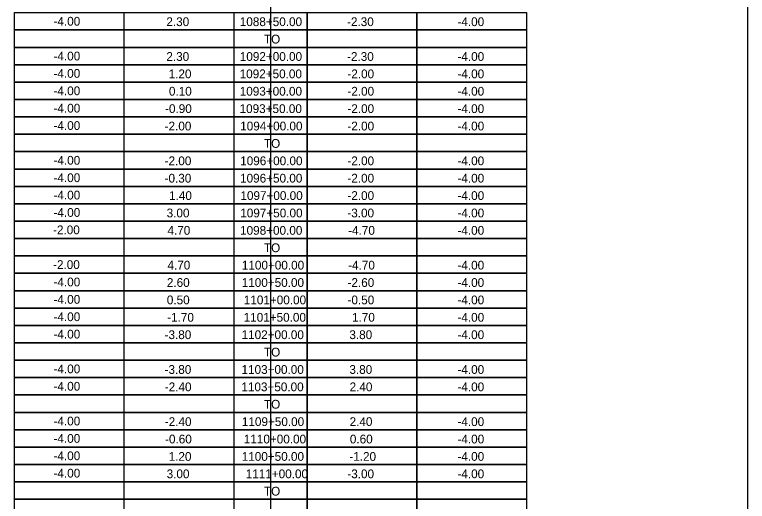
# Model space of a CAD drawing. Extents: x 1026502 to 1027102, y 781811 to 782040.
# Drawn here: x 1026950.62 to 1026990.71, y 781842.59 to 781869.21 of the extents above; entities that cross this region are included whole.
import ezdxf

# ---------------------------------------------------------------- set-up
doc = ezdxf.new("R2010")
doc.units = 0
doc.layers.add('BORDER', color=7, linetype='Continuous')
doc.layers.add('DIMENSIONS', color=7, linetype='Continuous')

msp = doc.modelspace()

# ---------------------------------------------------------------- linework, layer by layer
at = {"layer": 'BORDER'}
for p, q in [((1026964.619, 781922.543), (1026964.619, 781816.098)), ((1026990.71, 781922.543), (1026990.71, 781816.098)), ((1026953.619, 781868.37), (1026950.619, 781868.37)), ((1026953.619, 781868.37), (1026950.619, 781868.37)), ((1026953.619, 781868.37), (1026956.619, 781868.37)), ((1026953.619, 781867.419), (1026950.619, 781867.419)), ((1026953.619, 781867.419), (1026950.619, 781867.419)), ((1026953.619, 781867.419), (1026956.619, 781867.419)), ((1026953.619, 781866.469), (1026950.619, 781866.469)), ((1026953.619, 781866.469), (1026950.619, 781866.469)), ((1026953.619, 781866.469), (1026956.619, 781866.469)), ((1026953.619, 781865.519), (1026950.619, 781865.519)), ((1026953.619, 781865.519), (1026950.619, 781865.519)), ((1026953.619, 781865.519), (1026956.619, 781865.519)), ((1026953.619, 781864.568), (1026950.619, 781864.568)), ((1026953.619, 781864.568), (1026950.619, 781864.568)), ((1026953.619, 781864.568), (1026956.619, 781864.568)), ((1026953.619, 781863.618), (1026950.619, 781863.618)), ((1026953.619, 781863.618), (1026950.619, 781863.618)), ((1026953.619, 781863.618), (1026956.619, 781863.618)), ((1026953.619, 781862.667), (1026950.619, 781862.667)), ((1026953.619, 781862.667), (1026950.619, 781862.667)), ((1026953.619, 781862.667), (1026956.619, 781862.667)), ((1026953.619, 781861.717), (1026950.619, 781861.717)), ((1026953.619, 781861.717), (1026950.619, 781861.717)), ((1026953.619, 781861.717), (1026956.619, 781861.717)), ((1026953.619, 781860.767), (1026950.619, 781860.767)), ((1026953.619, 781860.767), (1026950.619, 781860.767)), ((1026953.619, 781860.767), (1026956.619, 781860.767)), ((1026953.619, 781859.816), (1026950.619, 781859.816)), ((1026953.619, 781859.816), (1026950.619, 781859.816)), ((1026953.619, 781859.816), (1026956.619, 781859.816)), ((1026953.619, 781858.866), (1026950.619, 781858.866)), ((1026953.619, 781858.866), (1026950.619, 781858.866)), ((1026953.619, 781858.866), (1026956.619, 781858.866)), ((1026953.619, 781857.915), (1026950.619, 781857.915)), ((1026953.619, 781857.915), (1026950.619, 781857.915)), ((1026953.619, 781857.915), (1026956.619, 781857.915)), ((1026953.619, 781856.965), (1026950.619, 781856.965)), ((1026953.619, 781856.965), (1026950.619, 781856.965)), ((1026953.619, 781856.965), (1026956.619, 781856.965)), ((1026953.619, 781856.015), (1026950.619, 781856.015)), ((1026953.619, 781856.015), (1026950.619, 781856.015)), ((1026953.619, 781856.015), (1026956.619, 781856.015)), ((1026953.619, 781855.064), (1026950.619, 781855.064)), ((1026953.619, 781855.064), (1026950.619, 781855.064)), ((1026953.619, 781855.064), (1026956.619, 781855.064)), ((1026953.619, 781854.114), (1026950.619, 781854.114)), ((1026953.619, 781854.114), (1026950.619, 781854.114)), ((1026953.619, 781854.114), (1026956.619, 781854.114)), ((1026953.619, 781853.163), (1026950.619, 781853.163)), ((1026953.619, 781853.163), (1026950.619, 781853.163)), ((1026953.619, 781853.163), (1026956.619, 781853.163)), ((1026953.619, 781852.213), (1026950.619, 781852.213)), ((1026953.619, 781852.213), (1026950.619, 781852.213)), ((1026953.619, 781852.213), (1026956.619, 781852.213)), ((1026953.619, 781851.263), (1026950.619, 781851.263)), ((1026953.619, 781851.263), (1026950.619, 781851.263)), ((1026953.619, 781851.263), (1026956.619, 781851.263)), ((1026953.619, 781850.312), (1026950.619, 781850.312)), ((1026953.619, 781850.312), (1026950.619, 781850.312)), ((1026953.619, 781850.312), (1026956.619, 781850.312)), ((1026953.619, 781849.362), (1026950.619, 781849.362)), ((1026953.619, 781849.362), (1026950.619, 781849.362)), ((1026953.619, 781849.362), (1026956.619, 781849.362)), ((1026953.619, 781848.411), (1026950.619, 781848.411)), ((1026953.619, 781848.411), (1026950.619, 781848.411)), ((1026953.619, 781848.411), (1026956.619, 781848.411)), ((1026953.619, 781847.461), (1026950.619, 781847.461)), ((1026953.619, 781847.461), (1026950.619, 781847.461)), ((1026953.619, 781847.461), (1026956.619, 781847.461)), ((1026953.619, 781846.511), (1026950.619, 781846.511)), ((1026953.619, 781846.511), (1026950.619, 781846.511)), ((1026953.619, 781846.511), (1026956.619, 781846.511)), ((1026953.619, 781845.56), (1026950.619, 781845.56)), ((1026953.619, 781845.56), (1026950.619, 781845.56)), ((1026953.619, 781845.56), (1026956.619, 781845.56)), ((1026953.619, 781844.61), (1026950.619, 781844.61)), ((1026953.619, 781844.61), (1026950.619, 781844.61)), ((1026953.619, 781844.61), (1026956.619, 781844.61)), ((1026953.619, 781843.659), (1026950.619, 781843.659)), ((1026953.619, 781843.659), (1026950.619, 781843.659)), ((1026953.619, 781843.659), (1026956.619, 781843.659)), ((1026953.619, 781842.709), (1026950.619, 781842.709)), ((1026953.619, 781842.709), (1026950.619, 781842.709)), ((1026953.619, 781842.709), (1026956.619, 781842.709))]:
    msp.add_line(p, q, dxfattribs=at)
for points in [[(1026950.619, 781869.32), (1026978.619, 781869.32), (1026978.619, 781868.37), (1026950.619, 781868.37)], [(1026950.619, 781868.37), (1026978.619, 781868.37), (1026978.619, 781867.419), (1026950.619, 781867.419)], [(1026950.619, 781867.419), (1026978.619, 781867.419), (1026978.619, 781866.469), (1026950.619, 781866.469)], [(1026950.619, 781866.469), (1026978.619, 781866.469), (1026978.619, 781865.519), (1026950.619, 781865.519)], [(1026950.619, 781865.519), (1026978.619, 781865.519), (1026978.619, 781864.568), (1026950.619, 781864.568)], [(1026950.619, 781864.568), (1026978.619, 781864.568), (1026978.619, 781863.618), (1026950.619, 781863.618)], [(1026950.619, 781863.618), (1026978.619, 781863.618), (1026978.619, 781862.667), (1026950.619, 781862.667)], [(1026950.619, 781862.667), (1026978.619, 781862.667), (1026978.619, 781861.717), (1026950.619, 781861.717)], [(1026950.619, 781861.717), (1026978.619, 781861.717), (1026978.619, 781860.767), (1026950.619, 781860.767)], [(1026950.619, 781860.767), (1026978.619, 781860.767), (1026978.619, 781859.816), (1026950.619, 781859.816)], [(1026950.619, 781859.816), (1026978.619, 781859.816), (1026978.619, 781858.866), (1026950.619, 781858.866)], [(1026950.619, 781858.866), (1026978.619, 781858.866), (1026978.619, 781857.915), (1026950.619, 781857.915)], [(1026950.619, 781857.915), (1026978.619, 781857.915), (1026978.619, 781856.965), (1026950.619, 781856.965)], [(1026950.619, 781856.965), (1026978.619, 781856.965), (1026978.619, 781856.015), (1026950.619, 781856.015)], [(1026950.619, 781856.015), (1026978.619, 781856.015), (1026978.619, 781855.064), (1026950.619, 781855.064)], [(1026950.619, 781855.064), (1026978.619, 781855.064), (1026978.619, 781854.114), (1026950.619, 781854.114)], [(1026950.619, 781854.114), (1026978.619, 781854.114), (1026978.619, 781853.163), (1026950.619, 781853.163)], [(1026950.619, 781853.163), (1026978.619, 781853.163), (1026978.619, 781852.213), (1026950.619, 781852.213)], [(1026950.619, 781852.213), (1026978.619, 781852.213), (1026978.619, 781851.263), (1026950.619, 781851.263)], [(1026950.619, 781851.263), (1026978.619, 781851.263), (1026978.619, 781850.312), (1026950.619, 781850.312)], [(1026950.619, 781850.312), (1026978.619, 781850.312), (1026978.619, 781849.362), (1026950.619, 781849.362)], [(1026950.619, 781849.362), (1026978.619, 781849.362), (1026978.619, 781848.411), (1026950.619, 781848.411)], [(1026950.619, 781848.411), (1026978.619, 781848.411), (1026978.619, 781847.461), (1026950.619, 781847.461)], [(1026950.619, 781847.461), (1026978.619, 781847.461), (1026978.619, 781846.511), (1026950.619, 781846.511)], [(1026950.619, 781846.511), (1026978.619, 781846.511), (1026978.619, 781845.56), (1026950.619, 781845.56)], [(1026950.619, 781845.56), (1026978.619, 781845.56), (1026978.619, 781844.61), (1026950.619, 781844.61)], [(1026950.619, 781844.61), (1026978.619, 781844.61), (1026978.619, 781843.659), (1026950.619, 781843.659)], [(1026950.619, 781843.659), (1026978.619, 781843.659), (1026978.619, 781842.709), (1026950.619, 781842.709)], [(1026950.619, 781842.709), (1026978.619, 781842.709), (1026978.619, 781841.759), (1026950.619, 781841.759)]]:
    msp.add_lwpolyline(points, close=True, dxfattribs=at)
for points in [[(1026962.619, 781869.32), (1026962.619, 781868.37), (1026956.619, 781868.37), (1026956.619, 781869.32)], [(1026966.619, 781869.32), (1026966.619, 781868.37), (1026962.619, 781868.37)], [(1026972.619, 781869.32), (1026972.619, 781868.37), (1026966.619, 781868.37), (1026966.619, 781869.32)], [(1026978.619, 781869.32), (1026978.619, 781868.37), (1026972.619, 781868.37), (1026972.619, 781869.32)], [(1026962.619, 781868.37), (1026962.619, 781867.419), (1026956.619, 781867.419), (1026956.619, 781868.37)], [(1026966.619, 781868.37), (1026966.619, 781867.419), (1026962.619, 781867.419)], [(1026972.619, 781868.37), (1026972.619, 781867.419), (1026966.619, 781867.419), (1026966.619, 781868.37)], [(1026978.619, 781868.37), (1026978.619, 781867.419), (1026972.619, 781867.419), (1026972.619, 781868.37)], [(1026962.619, 781867.419), (1026962.619, 781866.469), (1026956.619, 781866.469), (1026956.619, 781867.419)], [(1026966.619, 781867.419), (1026966.619, 781866.469), (1026962.619, 781866.469)], [(1026972.619, 781867.419), (1026972.619, 781866.469), (1026966.619, 781866.469), (1026966.619, 781867.419)], [(1026978.619, 781867.419), (1026978.619, 781866.469), (1026972.619, 781866.469), (1026972.619, 781867.419)], [(1026962.619, 781866.469), (1026962.619, 781865.519), (1026956.619, 781865.519), (1026956.619, 781866.469)], [(1026966.619, 781866.469), (1026966.619, 781865.519), (1026962.619, 781865.519)], [(1026972.619, 781866.469), (1026972.619, 781865.519), (1026966.619, 781865.519), (1026966.619, 781866.469)], [(1026978.619, 781866.469), (1026978.619, 781865.519), (1026972.619, 781865.519), (1026972.619, 781866.469)], [(1026962.619, 781865.519), (1026962.619, 781864.568), (1026956.619, 781864.568), (1026956.619, 781865.519)], [(1026966.619, 781865.519), (1026966.619, 781864.568), (1026962.619, 781864.568)], [(1026972.619, 781865.519), (1026972.619, 781864.568), (1026966.619, 781864.568), (1026966.619, 781865.519)], [(1026978.619, 781865.519), (1026978.619, 781864.568), (1026972.619, 781864.568), (1026972.619, 781865.519)], [(1026962.619, 781864.568), (1026962.619, 781863.618), (1026956.619, 781863.618), (1026956.619, 781864.568)], [(1026966.619, 781864.568), (1026966.619, 781863.618), (1026962.619, 781863.618)], [(1026972.619, 781864.568), (1026972.619, 781863.618), (1026966.619, 781863.618), (1026966.619, 781864.568)], [(1026978.619, 781864.568), (1026978.619, 781863.618), (1026972.619, 781863.618), (1026972.619, 781864.568)], [(1026962.619, 781863.618), (1026962.619, 781862.667), (1026956.619, 781862.667), (1026956.619, 781863.618)], [(1026966.619, 781863.618), (1026966.619, 781862.667), (1026962.619, 781862.667)], [(1026972.619, 781863.618), (1026972.619, 781862.667), (1026966.619, 781862.667), (1026966.619, 781863.618)], [(1026978.619, 781863.618), (1026978.619, 781862.667), (1026972.619, 781862.667), (1026972.619, 781863.618)], [(1026962.619, 781862.667), (1026962.619, 781861.717), (1026956.619, 781861.717), (1026956.619, 781862.667)], [(1026966.619, 781862.667), (1026966.619, 781861.717), (1026962.619, 781861.717)], [(1026972.619, 781862.667), (1026972.619, 781861.717), (1026966.619, 781861.717), (1026966.619, 781862.667)], [(1026978.619, 781862.667), (1026978.619, 781861.717), (1026972.619, 781861.717), (1026972.619, 781862.667)], [(1026962.619, 781861.717), (1026962.619, 781860.767), (1026956.619, 781860.767), (1026956.619, 781861.717)], [(1026966.619, 781861.717), (1026966.619, 781860.767), (1026962.619, 781860.767)], [(1026972.619, 781861.717), (1026972.619, 781860.767), (1026966.619, 781860.767), (1026966.619, 781861.717)], [(1026978.619, 781861.717), (1026978.619, 781860.767), (1026972.619, 781860.767), (1026972.619, 781861.717)], [(1026962.619, 781860.767), (1026962.619, 781859.816), (1026956.619, 781859.816), (1026956.619, 781860.767)], [(1026966.619, 781860.767), (1026966.619, 781859.816), (1026962.619, 781859.816)], [(1026972.619, 781860.767), (1026972.619, 781859.816), (1026966.619, 781859.816), (1026966.619, 781860.767)], [(1026978.619, 781860.767), (1026978.619, 781859.816), (1026972.619, 781859.816), (1026972.619, 781860.767)], [(1026962.619, 781859.816), (1026962.619, 781858.866), (1026956.619, 781858.866), (1026956.619, 781859.816)], [(1026966.619, 781859.816), (1026966.619, 781858.866), (1026962.619, 781858.866)], [(1026972.619, 781859.816), (1026972.619, 781858.866), (1026966.619, 781858.866), (1026966.619, 781859.816)], [(1026978.619, 781859.816), (1026978.619, 781858.866), (1026972.619, 781858.866), (1026972.619, 781859.816)], [(1026962.619, 781858.866), (1026962.619, 781857.915), (1026956.619, 781857.915), (1026956.619, 781858.866)], [(1026966.619, 781858.866), (1026966.619, 781857.915), (1026962.619, 781857.915)], [(1026972.619, 781858.866), (1026972.619, 781857.915), (1026966.619, 781857.915), (1026966.619, 781858.866)], [(1026978.619, 781858.866), (1026978.619, 781857.915), (1026972.619, 781857.915), (1026972.619, 781858.866)], [(1026962.619, 781857.915), (1026962.619, 781856.965), (1026956.619, 781856.965), (1026956.619, 781857.915)], [(1026966.619, 781857.915), (1026966.619, 781856.965), (1026962.619, 781856.965)], [(1026972.619, 781857.915), (1026972.619, 781856.965), (1026966.619, 781856.965), (1026966.619, 781857.915)], [(1026978.619, 781857.915), (1026978.619, 781856.965), (1026972.619, 781856.965), (1026972.619, 781857.915)], [(1026962.619, 781856.965), (1026962.619, 781856.015), (1026956.619, 781856.015), (1026956.619, 781856.965)], [(1026966.619, 781856.965), (1026966.619, 781856.015), (1026962.619, 781856.015)], [(1026972.619, 781856.965), (1026972.619, 781856.015), (1026966.619, 781856.015), (1026966.619, 781856.965)], [(1026978.619, 781856.965), (1026978.619, 781856.015), (1026972.619, 781856.015), (1026972.619, 781856.965)], [(1026962.619, 781856.015), (1026962.619, 781855.064), (1026956.619, 781855.064), (1026956.619, 781856.015)], [(1026966.619, 781856.015), (1026966.619, 781855.064), (1026962.619, 781855.064)], [(1026972.619, 781856.015), (1026972.619, 781855.064), (1026966.619, 781855.064), (1026966.619, 781856.015)], [(1026978.619, 781856.015), (1026978.619, 781855.064), (1026972.619, 781855.064), (1026972.619, 781856.015)], [(1026962.619, 781855.064), (1026962.619, 781854.114), (1026956.619, 781854.114), (1026956.619, 781855.064)], [(1026966.619, 781855.064), (1026966.619, 781854.114), (1026962.619, 781854.114)], [(1026972.619, 781855.064), (1026972.619, 781854.114), (1026966.619, 781854.114), (1026966.619, 781855.064)], [(1026978.619, 781855.064), (1026978.619, 781854.114), (1026972.619, 781854.114), (1026972.619, 781855.064)], [(1026962.619, 781854.114), (1026962.619, 781853.163), (1026956.619, 781853.163), (1026956.619, 781854.114)], [(1026966.619, 781854.114), (1026966.619, 781853.163), (1026962.619, 781853.163)], [(1026972.619, 781854.114), (1026972.619, 781853.163), (1026966.619, 781853.163), (1026966.619, 781854.114)], [(1026978.619, 781854.114), (1026978.619, 781853.163), (1026972.619, 781853.163), (1026972.619, 781854.114)], [(1026962.619, 781853.163), (1026962.619, 781852.213), (1026956.619, 781852.213), (1026956.619, 781853.163)], [(1026966.619, 781853.163), (1026966.619, 781852.213), (1026962.619, 781852.213)], [(1026972.619, 781853.163), (1026972.619, 781852.213), (1026966.619, 781852.213), (1026966.619, 781853.163)], [(1026978.619, 781853.163), (1026978.619, 781852.213), (1026972.619, 781852.213), (1026972.619, 781853.163)], [(1026962.619, 781852.213), (1026962.619, 781851.263), (1026956.619, 781851.263), (1026956.619, 781852.213)], [(1026966.619, 781852.213), (1026966.619, 781851.263), (1026962.619, 781851.263)], [(1026972.619, 781852.213), (1026972.619, 781851.263), (1026966.619, 781851.263), (1026966.619, 781852.213)], [(1026978.619, 781852.213), (1026978.619, 781851.263), (1026972.619, 781851.263), (1026972.619, 781852.213)], [(1026962.619, 781851.263), (1026962.619, 781850.312), (1026956.619, 781850.312), (1026956.619, 781851.263)], [(1026966.619, 781851.263), (1026966.619, 781850.312), (1026962.619, 781850.312)], [(1026972.619, 781851.263), (1026972.619, 781850.312), (1026966.619, 781850.312), (1026966.619, 781851.263)], [(1026978.619, 781851.263), (1026978.619, 781850.312), (1026972.619, 781850.312), (1026972.619, 781851.263)], [(1026962.619, 781850.312), (1026962.619, 781849.362), (1026956.619, 781849.362), (1026956.619, 781850.312)], [(1026966.619, 781850.312), (1026966.619, 781849.362), (1026962.619, 781849.362)], [(1026972.619, 781850.312), (1026972.619, 781849.362), (1026966.619, 781849.362), (1026966.619, 781850.312)], [(1026978.619, 781850.312), (1026978.619, 781849.362), (1026972.619, 781849.362), (1026972.619, 781850.312)], [(1026962.619, 781849.362), (1026962.619, 781848.411), (1026956.619, 781848.411), (1026956.619, 781849.362)], [(1026966.619, 781849.362), (1026966.619, 781848.411), (1026962.619, 781848.411)], [(1026972.619, 781849.362), (1026972.619, 781848.411), (1026966.619, 781848.411), (1026966.619, 781849.362)], [(1026978.619, 781849.362), (1026978.619, 781848.411), (1026972.619, 781848.411), (1026972.619, 781849.362)], [(1026962.619, 781848.411), (1026962.619, 781847.461), (1026956.619, 781847.461), (1026956.619, 781848.411)], [(1026966.619, 781848.411), (1026966.619, 781847.461), (1026962.619, 781847.461)], [(1026972.619, 781848.411), (1026972.619, 781847.461), (1026966.619, 781847.461), (1026966.619, 781848.411)], [(1026978.619, 781848.411), (1026978.619, 781847.461), (1026972.619, 781847.461), (1026972.619, 781848.411)], [(1026962.619, 781847.461), (1026962.619, 781846.511), (1026956.619, 781846.511), (1026956.619, 781847.461)], [(1026966.619, 781847.461), (1026966.619, 781846.511), (1026962.619, 781846.511)], [(1026972.619, 781847.461), (1026972.619, 781846.511), (1026966.619, 781846.511), (1026966.619, 781847.461)], [(1026978.619, 781847.461), (1026978.619, 781846.511), (1026972.619, 781846.511), (1026972.619, 781847.461)], [(1026962.619, 781846.511), (1026962.619, 781845.56), (1026956.619, 781845.56), (1026956.619, 781846.511)], [(1026966.619, 781846.511), (1026966.619, 781845.56), (1026962.619, 781845.56)], [(1026972.619, 781846.511), (1026972.619, 781845.56), (1026966.619, 781845.56), (1026966.619, 781846.511)], [(1026978.619, 781846.511), (1026978.619, 781845.56), (1026972.619, 781845.56), (1026972.619, 781846.511)], [(1026962.619, 781845.56), (1026962.619, 781844.61), (1026956.619, 781844.61), (1026956.619, 781845.56)], [(1026966.619, 781845.56), (1026966.619, 781844.61), (1026962.619, 781844.61)], [(1026972.619, 781845.56), (1026972.619, 781844.61), (1026966.619, 781844.61), (1026966.619, 781845.56)], [(1026978.619, 781845.56), (1026978.619, 781844.61), (1026972.619, 781844.61), (1026972.619, 781845.56)], [(1026962.619, 781844.61), (1026962.619, 781843.659), (1026956.619, 781843.659), (1026956.619, 781844.61)], [(1026966.619, 781844.61), (1026966.619, 781843.659), (1026962.619, 781843.659)], [(1026972.619, 781844.61), (1026972.619, 781843.659), (1026966.619, 781843.659), (1026966.619, 781844.61)], [(1026978.619, 781844.61), (1026978.619, 781843.659), (1026972.619, 781843.659), (1026972.619, 781844.61)], [(1026962.619, 781843.659), (1026962.619, 781842.709), (1026956.619, 781842.709), (1026956.619, 781843.659)], [(1026966.619, 781843.659), (1026966.619, 781842.709), (1026962.619, 781842.709)], [(1026972.619, 781843.659), (1026972.619, 781842.709), (1026966.619, 781842.709), (1026966.619, 781843.659)], [(1026978.619, 781843.659), (1026978.619, 781842.709), (1026972.619, 781842.709), (1026972.619, 781843.659)], [(1026962.619, 781842.709), (1026962.619, 781841.759), (1026956.619, 781841.759), (1026956.619, 781842.709)], [(1026966.619, 781842.709), (1026966.619, 781841.759), (1026962.619, 781841.759)], [(1026972.619, 781842.709), (1026972.619, 781841.759), (1026966.619, 781841.759), (1026966.619, 781842.709)], [(1026978.619, 781842.709), (1026978.619, 781841.759), (1026972.619, 781841.759), (1026972.619, 781842.709)]]:
    msp.add_lwpolyline(points, dxfattribs=at)

# ---------------------------------------------------------------- texts
at = {"layer": 'DIMENSIONS'}
for s, p in [('-4.00', (1026952.745, 781868.605)), ('2.30', (1026958.92, 781868.581)), ('1088+50.00', (1026962.937, 781868.581)), ('-2.30', (1026968.806, 781868.581)), ('-4.00', (1026974.848, 781868.581)), ('TO', (1026964.26, 781867.63)), ('-4.00', (1026952.745, 781866.704)), ('2.30', (1026958.92, 781866.679)), ('1092+00.00', (1026962.938, 781866.679)), ('-2.30', (1026968.806, 781866.679)), ('-4.00', (1026974.848, 781866.679)), ('-4.00', (1026952.745, 781865.754)), ('1.20', (1026959.044, 781865.729)), ('1092+50.00', (1026962.93, 781865.729)), ('-2.00', (1026968.825, 781865.729)), ('-4.00', (1026974.848, 781865.729)), ('-4.00', (1026952.745, 781864.803)), ('0.10', (1026959.06, 781864.778)), ('1093+00.00', (1026962.934, 781864.778)), ('-2.00', (1026968.825, 781864.778)), ('-4.00', (1026974.848, 781864.778)), ('-4.00', (1026952.745, 781863.853)), ('-0.90', (1026958.848, 781863.827)), ('1093+50.00', (1026962.926, 781863.827)), ('-2.00', (1026968.825, 781863.827)), ('-4.00', (1026974.848, 781863.827)), ('-4.00', (1026952.745, 781862.903)), ('-2.00', (1026958.825, 781862.876)), ('1094+00.00', (1026962.96, 781862.876)), ('-2.00', (1026968.825, 781862.876)), ('-4.00', (1026974.848, 781862.876)), ('TO', (1026964.26, 781861.925)), ('-4.00', (1026952.745, 781861.002)), ('-2.00', (1026958.825, 781860.974)), ('1096+00.00', (1026962.96, 781860.974)), ('-2.00', (1026968.825, 781860.974)), ('-4.00', (1026974.848, 781860.974)), ('-4.00', (1026952.745, 781860.051)), ('-0.30', (1026958.822, 781860.024)), ('1096+50.00', (1026962.953, 781860.024)), ('-2.00', (1026968.825, 781860.024)), ('-4.00', (1026974.848, 781860.024)), ('-4.00', (1026952.745, 781859.101)), ('1.40', (1026959.067, 781859.073)), ('1097+00.00', (1026962.972, 781859.073)), ('-2.00', (1026968.825, 781859.073)), ('-4.00', (1026974.848, 781859.073)), ('-4.00', (1026952.745, 781858.151)), ('3.00', (1026958.935, 781858.122)), ('1097+50.00', (1026962.964, 781858.122)), ('-3.00', (1026968.822, 781858.122)), ('-4.00', (1026974.848, 781858.122)), ('-2.00', (1026952.72, 781857.2)), ('4.70', (1026958.98, 781857.171)), ('1098+00.00', (1026962.953, 781857.171)), ('-4.70', (1026968.867, 781857.171)), ('-4.00', (1026974.848, 781857.171)), ('TO', (1026964.26, 781856.22)), ('-2.00', (1026952.72, 781855.299)), ('4.70', (1026958.98, 781855.269)), ('1100+00.00', (1026963.051, 781855.269)), ('-4.70', (1026968.867, 781855.269)), ('-4.00', (1026974.848, 781855.269)), ('-4.00', (1026952.745, 781854.349)), ('2.60', (1026958.946, 781854.319)), ('1100+50.00', (1026963.043, 781854.319)), ('-2.60', (1026968.833, 781854.319)), ('-4.00', (1026974.848, 781854.319)), ('-4.00', (1026952.745, 781853.399)), ('0.50', (1026958.946, 781853.368)), ('1101+00.00', (1026963.157, 781853.368)), ('-0.50', (1026968.833, 781853.368)), ('-4.00', (1026974.848, 781853.368)), ('-4.00', (1026952.745, 781852.448)), ('-1.70', (1026958.965, 781852.417)), ('1101+50.00', (1026963.149, 781852.417)), ('1.70', (1026969.078, 781852.417)), ('-4.00', (1026974.848, 781852.417)), ('-4.00', (1026952.745, 781851.498)), ('-3.80', (1026958.822, 781851.466)), ('1102+00.00', (1026963.036, 781851.466)), ('3.80', (1026968.935, 781851.466)), ('-4.00', (1026974.848, 781851.466)), ('TO', (1026964.26, 781850.515)), ('-4.00', (1026952.745, 781849.597)), ('-3.80', (1026958.822, 781849.564)), ('1103+00.00', (1026963.032, 781849.564)), ('3.80', (1026968.935, 781849.564)), ('-4.00', (1026974.848, 781849.564)), ('-4.00', (1026952.745, 781848.647)), ('-2.40', (1026958.833, 781848.614)), ('1103+50.00', (1026963.024, 781848.614)), ('2.40', (1026968.946, 781848.614)), ('-4.00', (1026974.848, 781848.614)), ('TO', (1026964.26, 781847.663)), ('-4.00', (1026952.745, 781846.746)), ('-2.40', (1026958.833, 781846.712)), ('1109+50.00', (1026963.051, 781846.712)), ('2.40', (1026968.946, 781846.712)), ('-4.00', (1026974.848, 781846.712)), ('-4.00', (1026952.745, 781845.795)), ('-0.60', (1026958.848, 781845.761)), ('1110+00.00', (1026963.157, 781845.761)), ('0.60', (1026968.961, 781845.761)), ('-4.00', (1026974.848, 781845.761)), ('-4.00', (1026952.745, 781844.845)), ('1.20', (1026959.044, 781844.81)), ('1100+50.00', (1026963.043, 781844.81)), ('-1.20', (1026968.931, 781844.81)), ('-4.00', (1026974.848, 781844.81)), ('-4.00', (1026952.745, 781843.895)), ('3.00', (1026958.935, 781843.859)), ('1111+00.00', (1026963.263, 781843.859)), ('-3.00', (1026968.822, 781843.859)), ('-4.00', (1026974.848, 781843.859)), ('TO', (1026964.26, 781842.909))]:
    msp.add_text(s, height=0.48, dxfattribs=at).set_placement(p)

doc.saveas('drawing.dxf')
